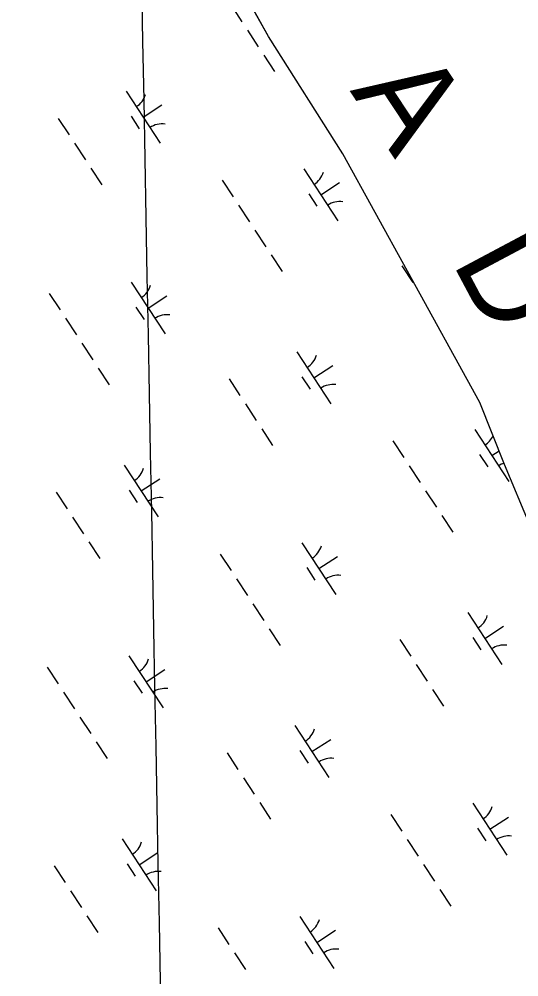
# Model space of a CAD drawing. Extents: x 3945642 to 3966284, y 206476 to 228921.
# Drawn here: x 3962226 to 3962628, y 214658 to 215429 of the extents above; entities that cross this region are included whole.
import ezdxf

# ---------------------------------------------------------------- set-up
doc = ezdxf.new("R2010")
doc.units = 0
for name, color, linetype in [('V-GRID-MAJR', 7, 'Continuous'), ('V-RIVR-IDEN', 7, 'Continuous'), ('V-TOPO-SHOR', 7, 'Continuous'), ('V-WETL-SWMP', 7, 'Continuous')]:
    doc.layers.add(name, color=color, linetype=linetype)

msp = doc.modelspace()

# ---------------------------------------------------------------- linework, layer by layer
at = {"layer": 'V-GRID-MAJR'}
msp.add_spline([(3962398.82, 211465.27), (3962380.88, 212428.56), (3962268.05, 218488.48), (3962267.27, 218530.32)], degree=3, dxfattribs=at)
at = {"layer": 'V-TOPO-SHOR'}
for points in [[(3962596.53, 215120.17), (3962538.23, 215226.12), (3962486.2, 215320.53), (3962426.39, 215415), (3962399.23, 215463.78), (3962344.02, 215551.39), (3962322.36, 215583.48), (3962304.75, 215608.71), (3962284.05, 215641.21), (3962253.16, 215685.1), (3962198.45, 215763.69), (3962169.75, 215807.02), (3962123.81, 215868.62), (3962087.49, 215916.5), (3962061.18, 215947.8), (3962031.61, 215983.49), (3962009.78, 216008.89), (3961992.8, 216026.2), (3961968.21, 216047.92), (3961939.27, 216072.68), (3961907.85, 216096.08), (3961870.85, 216121.16), (3961828.9, 216140.94), (3961793.45, 216157.39)], [(3963041.34, 213740.49), (3963031.11, 213761.64), (3962999.14, 213826.96), (3962982.75, 213867.23), (3962971.84, 213903.15), (3962953.43, 213961.63), (3962937.52, 214012.54), (3962924.96, 214061.41), (3962913.23, 214113.1), (3962895.2, 214186.39), (3962873.9, 214289.62), (3962854.85, 214371.14), (3962830.28, 214470.89), (3962797.12, 214591.72), (3962767.57, 214690.16), (3962738.9, 214781.46), (3962714.05, 214844.43), (3962681.22, 214919.99), (3962656.74, 214977.57), (3962636.99, 215020.97), (3962616.49, 215070.16), (3962596.53, 215120.17)]]:
    msp.add_lwpolyline(points, dxfattribs=at)
at = {"layer": 'V-WETL-SWMP'}
for p, q in [((3962426.39, 215414.99), (3962399.23, 215463.78)), ((3962396.27, 215440.25), (3962405.04, 215426.87)), ((3962409.42, 215420.17), (3962418.19, 215406.79)), ((3962486.2, 215320.53), (3962426.39, 215414.99)), ((3962422.57, 215400.1), (3962431.34, 215386.72)), ((3962311.82, 215370.94), (3962339.22, 215329.11)), ((3962325.52, 215350.02), (3962340.58, 215359.89)), ((3962257.13, 215349.1), (3962265.9, 215335.72)), ((3962315.78, 215350.82), (3962322.36, 215340.78)), ((3962270.28, 215329.02), (3962279.05, 215315.64)), ((3962538.23, 215226.12), (3962486.2, 215320.53)), ((3962283.44, 215308.95), (3962292.2, 215295.56)), ((3962454.9, 215308.39), (3962482.3, 215266.57)), ((3962389.1, 215299.27), (3962397.87, 215285.89)), ((3962468.6, 215287.48), (3962483.65, 215297.35)), ((3962458.86, 215288.27), (3962465.43, 215278.24)), ((3962402.26, 215279.19), (3962411.02, 215265.81)), ((3962415.41, 215259.12), (3962424.18, 215245.74)), ((3962428.56, 215239.04), (3962437.33, 215225.66)), ((3962533.79, 215230.33), (3962542.56, 215216.95)), ((3962596.53, 215120.17), (3962538.23, 215226.12)), ((3962315.76, 215217.24), (3962343.16, 215175.42)), ((3962249.96, 215208.12), (3962258.73, 215194.74)), ((3962329.46, 215196.33), (3962344.52, 215206.2)), ((3962546.94, 215210.26), (3962547.03, 215210.13)), ((3962319.72, 215197.12), (3962326.29, 215187.08)), ((3962263.12, 215188.04), (3962271.88, 215174.66)), ((3962276.27, 215167.97), (3962285.04, 215154.58)), ((3962449.34, 215161.02), (3962476.74, 215119.19)), ((3962289.42, 215147.89), (3962298.19, 215134.51)), ((3962463.04, 215140.11), (3962478.1, 215149.97)), ((3962394.65, 215139.18), (3962403.42, 215125.8)), ((3962453.3, 215140.9), (3962459.88, 215130.86)), ((3962407.8, 215119.1), (3962416.57, 215105.72)), ((3962616.49, 215070.16), (3962596.53, 215120.17)), ((3962420.96, 215099.03), (3962429.72, 215085.64)), ((3962592.42, 215098.48), (3962619.82, 215056.65)), ((3962526.62, 215089.35), (3962535.39, 215075.97)), ((3962596.38, 215078.35), (3962602.95, 215068.32)), ((3962606.12, 215077.56), (3962612, 215081.42)), ((3962310.21, 215069.87), (3962337.61, 215028.04)), ((3962539.78, 215069.28), (3962548.54, 215055.89)), ((3962637, 215020.97), (3962616.49, 215070.16)), ((3962323.91, 215048.95), (3962338.96, 215058.82)), ((3962255.51, 215048.03), (3962264.28, 215034.64)), ((3962314.16, 215049.74), (3962320.74, 215039.71)), ((3962552.93, 215049.2), (3962561.7, 215035.82)), ((3962566.08, 215029.12), (3962574.85, 215015.74)), ((3962268.67, 215027.95), (3962277.43, 215014.57)), ((3962281.82, 215007.88), (3962290.58, 214994.49)), ((3962453.28, 215007.32), (3962480.68, 214965.5)), ((3962387.49, 214998.2), (3962396.25, 214984.82)), ((3962466.98, 214986.41), (3962482.04, 214996.28)), ((3962457.24, 214987.2), (3962463.81, 214977.17)), ((3962400.64, 214978.12), (3962409.41, 214964.74)), ((3962413.79, 214958.05), (3962422.56, 214944.66)), ((3962586.86, 214951.1), (3962614.26, 214909.27)), ((3962426.94, 214937.97), (3962435.71, 214924.59)), ((3962600.56, 214930.19), (3962615.62, 214940.05)), ((3962532.17, 214929.26), (3962540.94, 214915.88)), ((3962590.82, 214930.98), (3962597.4, 214920.94)), ((3962314.14, 214916.17), (3962341.54, 214874.35)), ((3962248.35, 214907.05), (3962257.11, 214893.66)), ((3962327.84, 214895.26), (3962342.9, 214905.12)), ((3962545.32, 214909.18), (3962554.09, 214895.8)), ((3962318.1, 214896.05), (3962324.67, 214886.01)), ((3962261.5, 214886.97), (3962270.27, 214873.59)), ((3962558.48, 214889.11), (3962567.24, 214875.73)), ((3962274.65, 214866.9), (3962283.42, 214853.51)), ((3962447.73, 214859.95), (3962475.13, 214818.12)), ((3962287.8, 214846.82), (3962296.57, 214833.44)), ((3962461.43, 214839.03), (3962476.48, 214848.9)), ((3962393.03, 214838.11), (3962401.8, 214824.73)), ((3962451.68, 214839.83), (3962458.26, 214829.79)), ((3962406.19, 214818.03), (3962414.95, 214804.65)), ((3962419.34, 214797.96), (3962428.11, 214784.57)), ((3962590.8, 214797.41), (3962618.2, 214755.58)), ((3962525.01, 214788.28), (3962533.77, 214774.9)), ((3962604.5, 214776.49), (3962619.56, 214786.36)), ((3962594.76, 214777.28), (3962601.33, 214767.25)), ((3962308.59, 214768.8), (3962335.99, 214726.97)), ((3962538.16, 214768.21), (3962546.93, 214754.82)), ((3962322.29, 214747.88), (3962337.34, 214757.75)), ((3962253.9, 214746.96), (3962262.66, 214733.57)), ((3962312.55, 214748.67), (3962319.12, 214738.64)), ((3962551.31, 214748.13), (3962560.08, 214734.75)), ((3962564.46, 214728.05), (3962573.23, 214714.67)), ((3962267.05, 214726.88), (3962275.81, 214713.5)), ((3962280.2, 214706.81), (3962288.97, 214693.42)), ((3962451.66, 214706.25), (3962479.06, 214664.43)), ((3962385.87, 214697.13), (3962394.63, 214683.75)), ((3962465.36, 214685.34), (3962480.42, 214695.21)), ((3962455.62, 214686.13), (3962462.19, 214676.09)), ((3962399.02, 214677.05), (3962407.79, 214663.67))]:
    msp.add_line(p, q, dxfattribs=at)
for centre, start, end in [((3962310.59, 215373.26), 302.45745, 344.00111), ((3962340.86, 215327.05), 82.45745, 124.00111), ((3962453.66, 215310.72), 302.45745, 344.00111), ((3962483.93, 215264.51), 82.45745, 124.00111), ((3962314.52, 215219.57), 302.45745, 344.00111), ((3962344.79, 215173.36), 82.45745, 124.00111), ((3962448.11, 215163.34), 302.45745, 344.00111), ((3962478.38, 215117.13), 82.45745, 124.00111), ((3962591.18, 215100.8), 302.45745, 335.33728), ((3962308.97, 215072.19), 302.45745, 344.00111), ((3962621.45, 215054.59), 107.97228, 124.00111), ((3962339.24, 215025.98), 82.45745, 124.00111), ((3962452.04, 215009.65), 302.45745, 344.00111), ((3962482.31, 214963.44), 82.45745, 124.00111), ((3962585.63, 214953.42), 302.45745, 344.00111), ((3962615.9, 214907.21), 82.45745, 124.00111), ((3962312.9, 214918.5), 302.45745, 344.00111), ((3962343.18, 214872.29), 82.45745, 124.00111), ((3962446.49, 214862.27), 302.45745, 344.00111), ((3962476.76, 214816.06), 82.45745, 124.00111), ((3962589.56, 214799.73), 302.45745, 344.00111), ((3962307.35, 214771.12), 302.45745, 344.00111), ((3962619.83, 214753.52), 82.45745, 124.00111), ((3962337.62, 214724.91), 82.45745, 124.00111), ((3962450.42, 214708.58), 302.45745, 344.00111), ((3962480.7, 214662.37), 82.45745, 124.00111)]:
    msp.add_arc(centre, 17.62, start, end, dxfattribs=at)

# ---------------------------------------------------------------- texts
at = {"layer": 'V-RIVR-IDEN'}
for s, rotation, p in [('A', 303.45316, (3962491.61, 215371.36)), ('D', 298.04456, (3962573.63, 215233.76))]:
    msp.add_text(s, height=75, rotation=rotation, dxfattribs=at).set_placement(p)

doc.saveas('drawing.dxf')
